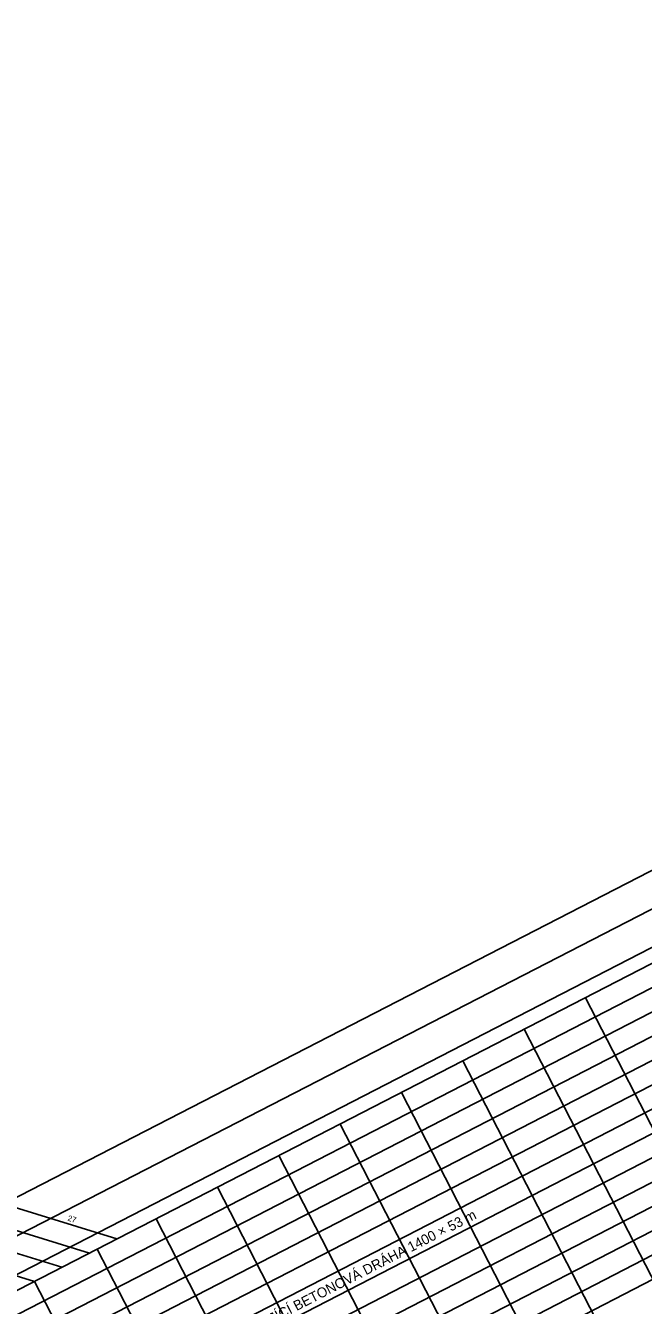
# Model space of a CAD drawing. Extents: x -886320 to -884760, y -1024172 to -1023483.
# Drawn here: x -885881.5 to -885773.4, y -1024051.4 to -1023827.5 of the extents above; entities that cross this region are included whole.
import ezdxf

# ---------------------------------------------------------------- set-up
doc = ezdxf.new("R2010")
doc.units = 0
for name, color, linetype in [('AGA__Netisknout', 7, 'Continuous'), ('Stavajici_betonova_draha', 7, 'Continuous'), ('Stavajici_betonova_draha_osa', 7, 'Continuous'), ('Stavajici_betonova_draha_popis', 7, 'Continuous'), ('Stavajici_betonova_draha_Popis desky', 7, 'Continuous'), ('Stavajici_betonova_draha_Spára', 7, 'Continuous'), ('Stavajici_drahovy_system_TWY', 7, 'Continuous'), ('Stavajici_drahovy_system_TWY_osy', 7, 'Continuous')]:
    doc.layers.add(name, color=color, linetype=linetype)

msp = doc.modelspace()

# ---------------------------------------------------------------- linework, layer by layer
at = {"layer": 'AGA__Netisknout'}
msp.add_line((-886017.78, -1024147.99), (-884773.13, -1023507.02), dxfattribs=at)
at = {"layer": 'Stavajici_betonova_draha'}
for p, q in [((-886029.69, -1024124.32), (-884785.04, -1023483.35)), ((-886029.69, -1024124.32), (-884785.04, -1023483.35)), ((-886315.74, -1023900.86), (-885865.51, -1024039.77))]:
    msp.add_line(p, q, dxfattribs=at)
at = {"layer": 'Stavajici_betonova_draha_osa'}
msp.add_line((-886017.55, -1024147.88), (-884772.9, -1023506.91), dxfattribs=at)
at = {"layer": 'Stavajici_betonova_draha_Spára'}
for p, q in [((-886029.91, -1024124.43), (-884785.26, -1023483.46)), ((-886028.18, -1024127.8), (-884783.53, -1023486.82)), ((-886026.44, -1024131.16), (-884781.79, -1023490.19)), ((-886024.71, -1024134.53), (-884780.06, -1023493.56)), ((-886022.98, -1024137.89), (-884778.33, -1023496.92)), ((-886021.24, -1024141.26), (-884776.59, -1023500.29)), ((-886019.51, -1024144.63), (-884774.86, -1023503.65)), ((-886016.04, -1024151.36), (-884771.39, -1023510.39)), ((-886014.31, -1024154.72), (-884769.66, -1023513.75)), ((-886012.58, -1024158.09), (-884767.93, -1023517.12)), ((-886010.84, -1024161.46), (-884766.19, -1023520.48)), ((-886009.11, -1024164.82), (-884764.46, -1023523.85)), ((-886007.38, -1024168.19), (-884762.73, -1023527.21)), ((-885865.51, -1024039.77), (-886315.74, -1023900.86)), ((-885870.32, -1024042.24), (-886316.86, -1023904.48)), ((-885875.13, -1024044.72), (-886317.98, -1023908.1)), ((-885879.94, -1024047.2), (-886319.09, -1023911.72)), ((-885783.56, -1023997.57), (-885759.29, -1024044.69)), ((-885794.29, -1024003.09), (-885770.02, -1024050.21)), ((-885805.02, -1024008.62), (-885780.75, -1024055.74)), ((-885815.75, -1024014.14), (-885791.48, -1024061.27)), ((-885826.48, -1024019.67), (-885802.21, -1024066.79)), ((-885837.21, -1024025.19), (-885812.94, -1024072.32)), ((-885847.94, -1024030.72), (-885823.67, -1024077.84)), ((-885858.67, -1024036.25), (-885834.4, -1024083.37)), ((-885868.96, -1024041.55), (-885844.7, -1024088.67)), ((-885879.94, -1024047.2), (-885855.67, -1024094.32))]:
    msp.add_line(p, q, dxfattribs=at)
at = {"layer": 'Stavajici_drahovy_system_TWY'}
for p, q in [((-885887.27, -1024034.67), (-884885.91, -1023518.99)), ((-885886.13, -1024047.58), (-885758.79, -1023982))]:
    msp.add_line(p, q, dxfattribs=at)
at = {"layer": 'Stavajici_drahovy_system_TWY_osy'}
msp.add_line((-885886.7, -1024041.13), (-884883.17, -1023524.32), dxfattribs=at)

# ---------------------------------------------------------------- texts
at = {"layer": 'Stavajici_betonova_draha_popis'}
msp.add_text('STÁVAJÍCÍ BETONOVÁ DRÁHA 1400 × 53 m', height=1.75, rotation=27.2477, dxfattribs=at).set_placement((-885845.17, -1024058.12))
at = {"layer": 'Stavajici_betonova_draha_Popis desky'}
msp.add_text('27', height=1, rotation=342.8547, dxfattribs=at).set_placement((-885874.22, -1024036.55))

doc.saveas('drawing.dxf')
